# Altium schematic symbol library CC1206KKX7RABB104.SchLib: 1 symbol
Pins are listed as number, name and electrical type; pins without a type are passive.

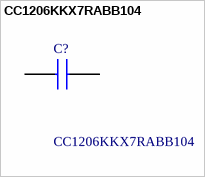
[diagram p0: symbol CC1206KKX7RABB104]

## CC1206KKX7RABB104
designator C?
Multilayer Ceramic Capacitors MLCC - SMD/SMT 200V 0.1uF X7R 1206 10%; Manufacturer_Name: YAGEO; Geometry.Height: 1.8mm
footprint CAPC3216X180N
pins: 1, 2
